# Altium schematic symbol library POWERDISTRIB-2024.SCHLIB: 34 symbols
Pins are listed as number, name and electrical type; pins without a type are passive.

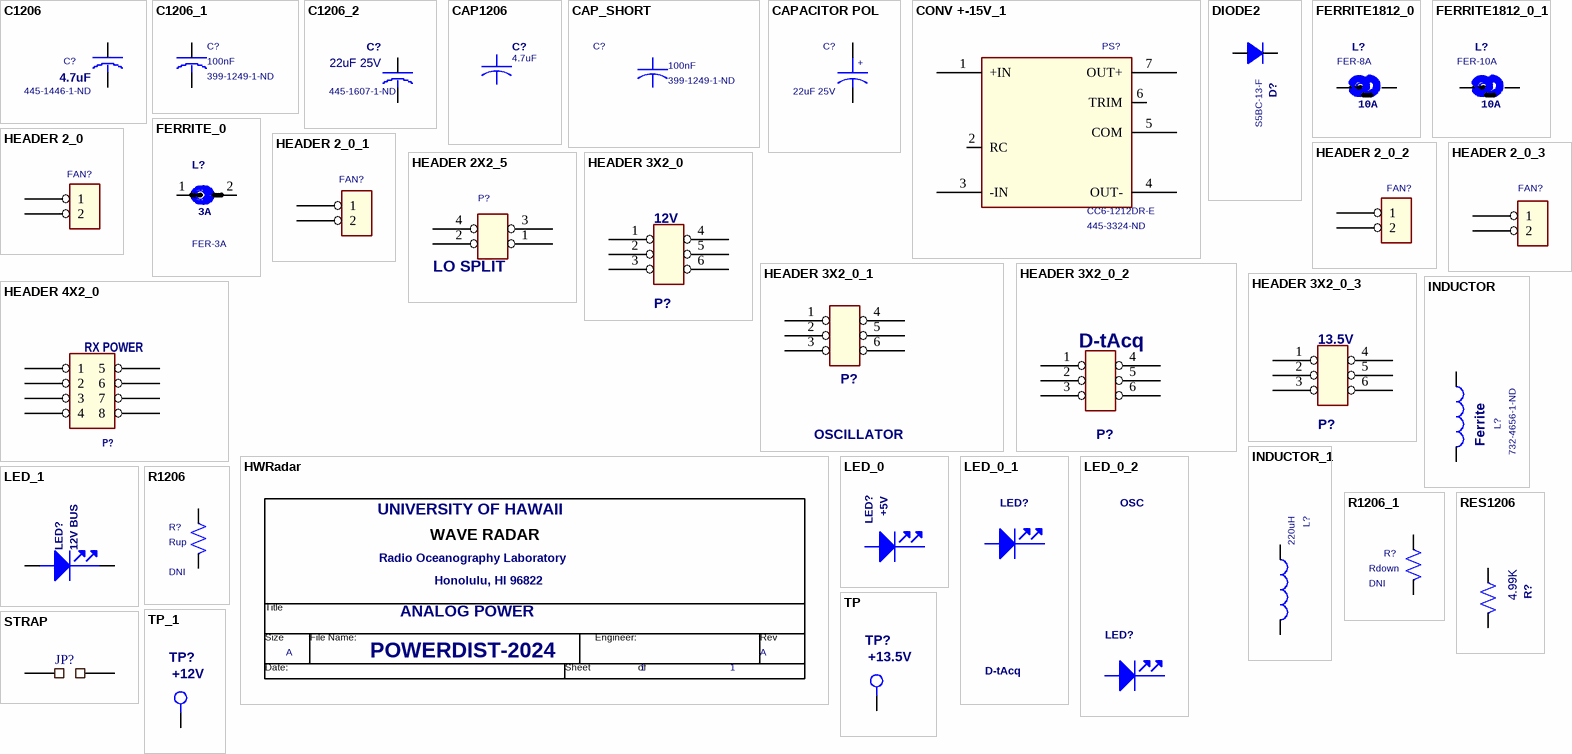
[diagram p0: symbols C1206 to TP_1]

## C1206
designator C?, comment 4.7uF  DK Stock: 445-1446-1-ND
footprint 1812 (Chip Capacitor; Body 4.5 x 3.2 mm (LxW typ))
footprint C1812
pins: 1, 2

## C1206_1
designator C?, comment 100nF  DK Stock: 399-1249-1-ND
footprint 1206 (Footprint not found)
pins: 1, 2

## C1206_2
designator C?, comment 22uF 25V  DK Stock: 445-1607-1-ND
footprint 1812 (Chip Capacitor; Body 4.5 x 3.2 mm (LxW typ))
footprint C1812
pins: 1, 2

## CAP1206
designator C?, comment 4.7uF
DK Stock: 445-1446-1-ND
footprint 1812 (Chip Capacitor; Body 4.5 x 3.2 mm (LxW typ))
footprint C1812
pins: 1, 2

## CAP_SHORT
designator C?, comment 100nF  DK Stock: 399-1249-1-ND
footprint 1206 (Footprint not found)
footprint C1206
pins: 1, 2

## CAPACITOR POL
designator C?, comment 22uF 25V
DK Stock: 445-1607-1-ND
footprint 1812 (Chip Capacitor; Body 4.5 x 3.2 mm (LxW typ))
pins: 1, 2

## CONV +-15V_1
designator PS?, comment CC6-1212DR-E  DK Stock: 445-3324-ND
footprint DCDC-CC6/B
pins: 1 +IN, 2 RC, 3 -IN, 4 OUT-, 5 COM, 6 TRIM, 7 OUT+

## DIODE2
designator D?, comment S5BC-13-F
DK Stock: S5BC-FDICT-ND
footprint SMC (Footprint not found)
pins: A ANOD, K CATH

## FERRITE1812_0
designator L?, comment FER-8A
DK Stock: 240-2433-1-ND
footprint 2220 (Chip Resistor; Body 5.7 x 5 mm (LxW typ))
footprint L2220
pins: 1 L1, 2 L2

## FERRITE1812_0_1
designator L?, comment FER-10A
DK Stock: 240-2511-1-ND
footprint l3318
footprint L3318
pins: 1 L1, 2 L2

## FERRITE_0
designator L?, comment FER-3A
DK Stock: 587-1759-1-ND
footprint 1812 (Footprint not found)
pins: 1 L1, 2 L2

## HEADER 2_0
designator FAN?, comment FAN1  (value not drawn)
DK Stock: A30931-ND
footprint SIP2-SHRD
pins: 1, 2

## HEADER 2_0_1
designator FAN?, comment FAN2  (value not drawn)
DK Stock: A30931-ND
footprint SIP2-SHRD
pins: 1, 2

## HEADER 2_0_2
designator FAN?, comment FAN4  (value not drawn)
DK Stock: A30931-ND
footprint SIP2-SHRD
pins: 1, 2

## HEADER 2_0_3
designator FAN?, comment FAN3  (value not drawn)
DK Stock: A30931-ND
footprint SIP2-SHRD
pins: 1, 2

## HEADER 2X2_5
designator P?, comment LO SPLIT
DK Stock: WM3801-ND
footprint MFTJR2X2
pins: 1, 2, 3, 4

## HEADER 3X2_0
designator P?, comment 12V
DK Stock: WM3802-ND
footprint MFTJR2X3
pins: 1, 2, 3, 4, 5, 6

## HEADER 3X2_0_1
designator P?, comment OSCILLATOR
DK Stock: WM3802-ND
footprint MFTJR2X3
pins: 1, 2, 3, 4, 5, 6

## HEADER 3X2_0_2
designator P?, comment D-tAcq
DK Stock: WM3802-ND
footprint MFTJR2X3
pins: 1, 2, 3, 4, 5, 6

## HEADER 3X2_0_3
designator P?, comment 13.5V
DK Stock: WM3802-ND
footprint MFTJR2X3
pins: 1, 2, 3, 4, 5, 6

## HEADER 4X2_0
designator P?, comment RX POWER
DK Stock: WM3803-ND
footprint MFTJR2X4
pins: 1, 2, 3, 4, 5, 6, 7, 8

## HWRadar
designator *?  Doc: POWERDIST-2024  RevCode: A  Title: ANALOG POWER  OrgName: UNIVERSITY OF HAWAII  OrgAddr1: Radio Oceanography Laboratory  OrgAddr3: Honolulu, HI 96822  Page Number: 1  (hidden comment: HWRadar)  (graphical)
Engineer:: <ENG>; OrgAddr2: 2525 Correa Road

## INDUCTOR
designator L?, comment Ferrite  DK Stock: 732-4656-1-ND
footprint 1206 (Footprint not found)
pins: 1, 2

## INDUCTOR_1
designator L?, comment 220uH
DK Stock: DN7942CT-ND
footprint 1812 (Footprint not found)
pins: 1, 2

## LED_0
designator LED?, comment +5V
DK Stock: 754-1445-1-ND
footprint LED1206
pins: 1 ANODE, 2 CATHODE

## LED_0_1
designator LED?, comment D-tAcq
DK Stock: 754-1445-1-ND
footprint LED1206
pins: 1 ANODE, 2 CATHODE

## LED_0_2
designator LED?, comment OSC
DK Stock: 754-1445-1-ND
footprint LED1206
pins: 1 ANODE, 2 CATHODE

## LED_1
designator LED?, comment 12V BUS
DK Stock: 754-1445-1-ND
footprint LED1206
pins: 1 ANODE, 2 CATHODE

## R1206
designator R?, comment Rup  DK Stock: DNI
footprint 1206 (Footprint not found)
pins: 1, 2

## R1206_1
designator R?, comment Rdown  DK Stock: DNI
footprint 1206 (Footprint not found)
pins: 1, 2

## RES1206
designator R?, comment 4.99K
DK Stock: 311-2.49KFRCT-ND
footprint 1206 (Footprint not found)
pins: 1, 2

## STRAP
designator JP?
footprint 2X2.54
pins: 1, 2

## TP
designator TP?, comment +13.5V
DK Stock: NS
footprint TP
pins: TP

## TP_1
designator TP?, comment +12V
DK Stock: NS
footprint TP
pins: TP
